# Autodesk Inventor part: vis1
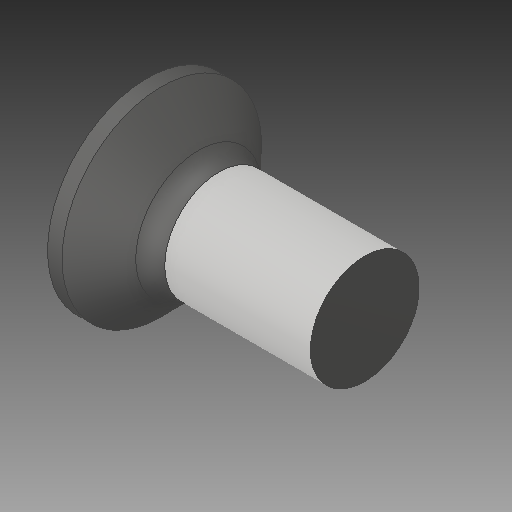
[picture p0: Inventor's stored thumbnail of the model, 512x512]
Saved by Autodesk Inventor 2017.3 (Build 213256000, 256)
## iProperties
Created: 1999-08
Part Number: vis1
Material: Générique
Document SubType Name: Modeling
Designer: ficho
Density: 1 g/cm^3
Appearance: Par défaut
Author: ficho
Sending System: SolidWorks 2009
Last Author: tof
Last Saved: 2010-07-07
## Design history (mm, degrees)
feature "RecessCore"
node "Solide1"
